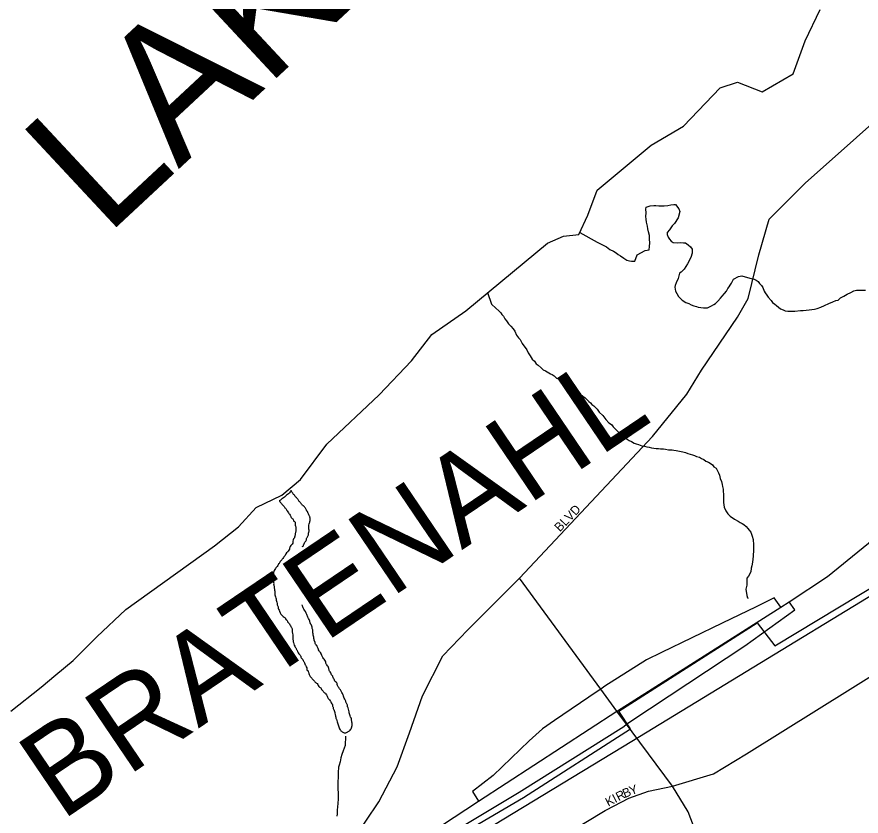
# Model space of a CAD drawing. Extents: x 2139079 to 2262683, y 1235796 to 1334992.
# Drawn here: x 2210756 to 2215487, y 1294375 to 1298857 of the extents above; entities that cross this region are included whole.
import ezdxf

# ---------------------------------------------------------------- set-up
doc = ezdxf.new("R2010")
doc.units = 0
for name, color, linetype in [('GM_X_City_Street', 7, 'Continuous'), ('GM_X_City_Street_Text', 7, 'Continuous'), ('GM_X_Interchange_Ramps', 7, 'Continuous'), ('GM_X_Interstate_Route', 7, 'Continuous'), ('GM_X_Major_Lake', 7, 'Continuous'), ('GM_X_Major_Lake_Text', 7, 'Continuous'), ('GM_X_Major_River', 7, 'Continuous'), ('GM_X_Minor_River', 7, 'Continuous'), ('GM_X_Rail_Line', 7, 'Continuous'), ('GM_X_State_Route', 7, 'Continuous')]:
    doc.layers.add(name, color=color, linetype=linetype)

msp = doc.modelspace()

# ---------------------------------------------------------------- linework, layer by layer
at = {"layer": 'GM_X_City_Street'}
for points in [[(2210765.7, 1293921.8), (2211801.2, 1293964.2), (2212304.8, 1294027), (2212399.2, 1294027), (2212466.8, 1294063.6), (2212638.5, 1294238.9), (2212784.6, 1294454.5), (2212886.8, 1294651.8), (2212956.2, 1294841.7), (2213029.3, 1295050), (2213142.5, 1295274.2), (2213283.1, 1295420.4), (2213573.5, 1295709), (2214317.9, 1296503.1), (2214511.4, 1296741.1), (2214593.2, 1296875), (2214794.1, 1297172.5), (2214853.5, 1297276.5), (2214913.2, 1297522), (2214972.6, 1297722.9), (2215173.4, 1297923.7), (2216341.1, 1298964.8), (2217218.8, 1299790.1), (2218141.2, 1300729.6)], [(2214060.3, 1294410.5), (2214185.1, 1294475.3), (2214295.7, 1294515.8), (2214429.8, 1294543.9), (2214660.6, 1294612.1), (2214845, 1294724.7), (2215629.5, 1295214.2), (2216726.2, 1295837.1), (2216761.4, 1295820.7)], [(2214027.8, 1295087.7), (2213573.5, 1295709)], [(2214203.9, 1294848.4), (2214173, 1294890.1), (2214118.6, 1294963.4), (2214027.8, 1295087.7)], [(2214644.6, 1293875.9), (2214639.6, 1293941.7), (2214628.6, 1294036), (2214601.9, 1294178), (2214518.7, 1294400), (2214429.8, 1294543.9), (2214203.9, 1294848.4)], [(2213265.1, 1293941.8), (2213266.3, 1293942.4), (2213845.7, 1294282), (2214053.1, 1294406.7), (2214060.3, 1294410.5)]]:
    msp.add_lwpolyline(points, dxfattribs=at)
at = {"layer": 'GM_X_Interchange_Ramps'}
for points in [[(2215037.1, 1295546.6), (2215000.7, 1295599.9), (2214898.3, 1295548.6), (2214709.2, 1295456.2), (2214367.8, 1295292.1), (2214283.8, 1295251), (2214050.7, 1295103), (2214027.8, 1295087.7)], [(2214173, 1294890.1), (2214195.9, 1294907.6), (2214836.1, 1295329.5), (2215115.1, 1295530.9), (2215084, 1295576.3)], [(2214027.8, 1295087.7), (2214007.8, 1295074.4), (2213768.2, 1294910.7), (2213702.4, 1294864.2), (2213626, 1294797), (2213425.5, 1294602.7), (2213309.6, 1294512.2), (2213343.6, 1294459.2)], [(2213134.5, 1294323.1), (2213168.7, 1294267.8), (2213571, 1294509.8), (2214156.8, 1294877.8), (2214173, 1294890.1)]]:
    msp.add_lwpolyline(points, dxfattribs=at)
at = {"layer": 'GM_X_Interstate_Route'}
for points in [[(2214122.3, 1294965.7), (2215037.1, 1295546.6), (2215084, 1295576.3), (2215299.7, 1295719.1), (2215728.5, 1296068), (2216029.7, 1296395.8), (2216265.8, 1296723.6), (2216403.8, 1296975), (2216521.9, 1297234.3), (2216598.9, 1297455.1), (2216727.2, 1297870.3), (2216829.9, 1298168.1), (2216968.5, 1298444.6), (2217135.4, 1298719.3)], [(2209268.7, 1291750.6), (2210765.4, 1292746), (2211168.5, 1293011), (2211346.1, 1293126.4), (2211567.6, 1293268.1), (2211821.2, 1293415.9), (2213292.4, 1294301), (2213595.9, 1294479.3), (2214194.6, 1294863.9), (2214129.9, 1294963.8), (2214905.3, 1295458), (2215003.2, 1295329.9), (2217276.8, 1296701.3)], [(2207701.2, 1290838), (2207916.4, 1290971.4), (2210778.7, 1292838.5), (2212470.3, 1293891), (2213134.5, 1294323.1), (2213343.6, 1294459.2), (2214118.6, 1294963.4), (2214122.3, 1294965.7)]]:
    msp.add_lwpolyline(points, dxfattribs=at)
at = {"layer": 'GM_X_Major_Lake'}
msp.add_lwpolyline([(2210722.2, 1294964.2), (2210891.3, 1295098.5), (2210972.9, 1295167.6), (2211070.4, 1295247), (2211203.4, 1295380.9), (2211366.3, 1295533.2), (2211862.2, 1295889.9), (2211997.5, 1295997.8), (2212096.7, 1296105.2), (2212240.5, 1296175), (2212345.9, 1296262.5), (2212492.3, 1296460.8), (2212786.3, 1296737.1), (2212966.9, 1296927.8), (2213081.7, 1297075.6), (2213270.9, 1297208.1), (2213730.4, 1297588.5), (2213818.3, 1297627.6), (2213904.5, 1297636.6), (2213955.5, 1297745.6), (2214008.2, 1297884.7), (2214310.5, 1298136.9), (2214492, 1298243.3), (2214696.4, 1298458.3), (2214794.4, 1298489.5), (2214933.5, 1298436.7), (2215107, 1298537), (2215173.2, 1298722.4), (2215257.6, 1298898)], dxfattribs=at)
at = {"layer": 'GM_X_Major_River'}
for points in [[(2212292.7, 1296200.8), (2212286.4, 1296193), (2212278.5, 1296182.9), (2212266.6, 1296174.8), (2212254.6, 1296162.6), (2212244.7, 1296156.5), (2212228.8, 1296144.3), (2212226.4, 1296142.8)], [(2212341, 1296137.2), (2212334.9, 1296143.2), (2212332.9, 1296149.2), (2212326.8, 1296155.2), (2212322.8, 1296161.2), (2212314.7, 1296167.1), (2212312.6, 1296173.1), (2212306.6, 1296179.1), (2212302.5, 1296185.1), (2212296.4, 1296193.1), (2212294.4, 1296199.1), (2212292.7, 1296200.8)], [(2212226.4, 1296142.8), (2212226.8, 1296142.3), (2212230.8, 1296136.3), (2212236.9, 1296130.4), (2212241, 1296124.4), (2212247, 1296118.4), (2212253.1, 1296110.4), (2212257.2, 1296104.4), (2212263.2, 1296100.4), (2212267.3, 1296092.4), (2212271.3, 1296086.4), (2212277.4, 1296076.5), (2212289.6, 1296058.5), (2212291.7, 1296052.5), (2212295.7, 1296046.5), (2212301.8, 1296042.5), (2212305.9, 1296034.5), (2212307.9, 1296028.5), (2212313.9, 1296026.6), (2212316, 1296020.6), (2212316.1, 1296006.5), (2212318.2, 1295996.5), (2212318.4, 1295970.3), (2212316.5, 1295964.3), (2212314.6, 1295956.3), (2212314.6, 1295950.2), (2212312.7, 1295944.2), (2212310.7, 1295936.1), (2212306.8, 1295930.1), (2212302.9, 1295916), (2212302.9, 1295910), (2212291.1, 1295891.8), (2212285.2, 1295881.7), (2212283.2, 1295871.7), (2212275.3, 1295861.6), (2212271.4, 1295855.5), (2212263.4, 1295845.4), (2212259.5, 1295837.3), (2212253.5, 1295831.2), (2212249.6, 1295825.2), (2212241.7, 1295815.1), (2212237.7, 1295809), (2212231.8, 1295803), (2212227.8, 1295794.9), (2212221.9, 1295788.8), (2212217.9, 1295780.8), (2212210, 1295770.6), (2212204.1, 1295762.6), (2212198.1, 1295752.5), (2212194.2, 1295740.4), (2212194.4, 1295722.3), (2212192.5, 1295716.3), (2212192.7, 1295692.2), (2212194.8, 1295682.1), (2212194.8, 1295672.1), (2212196.9, 1295664.1), (2212197, 1295658.1), (2212199, 1295650.1), (2212199.1, 1295644), (2212201.2, 1295638), (2212201.3, 1295622), (2212207.5, 1295597.9), (2212209.6, 1295591.9), (2212209.7, 1295579.8), (2212213.8, 1295567.8), (2212213.9, 1295559.8), (2212217.9, 1295551.8), (2212220, 1295545.8), (2212220.1, 1295539.8), (2212226.1, 1295529.8), (2212228.2, 1295523.8), (2212248.5, 1295493.8), (2212256.6, 1295487.9), (2212264.7, 1295475.9), (2212270.7, 1295471.9), (2212272.8, 1295463.9), (2212278.9, 1295457.9), (2212291.1, 1295437.9), (2212295.1, 1295431.9), (2212299.2, 1295419.9), (2212299.3, 1295407.9), (2212301.5, 1295391.8), (2212301.5, 1295385.8), (2212301.6, 1295375.8), (2212301.7, 1295369.8), (2212303.8, 1295361.7), (2212303.8, 1295355.7), (2212305.9, 1295347.7), (2212310, 1295333.7), (2212316.1, 1295321.7), (2212320.2, 1295315.7), (2212322.2, 1295309.7), (2212326.3, 1295303.7), (2212328.3, 1295297.7), (2212336.5, 1295285.7), (2212342.6, 1295277.7), (2212346.6, 1295271.7)], [(2212356.9, 1295885.9), (2212357.2, 1295886.3), (2212361.2, 1295892.4), (2212363.1, 1295898.4), (2212367.1, 1295906.5), (2212373, 1295914.6), (2212377, 1295920.6), (2212378.9, 1295926.7), (2212380.9, 1295934.7), (2212384.8, 1295940.8), (2212388.7, 1295948.8), (2212390.7, 1295954.9), (2212390.9, 1295956.9), (2212390.7, 1295958.9), (2212390.5, 1295960.9), (2212390.6, 1295962.9), (2212391, 1295964.4), (2212391.6, 1295965.9), (2212392.2, 1295967.4), (2212392.6, 1295969), (2212392.9, 1295978.4), (2212391.9, 1295988.1), (2212391.2, 1295997.7), (2212392.2, 1296007.1), (2212396.1, 1296019.2), (2212398.1, 1296027.2), (2212397.9, 1296051.3), (2212395.8, 1296057.3), (2212387.6, 1296073.3), (2212385.6, 1296079.4), (2212381.5, 1296085.3), (2212375.4, 1296097.3), (2212369.3, 1296105.3), (2212365.3, 1296111.3), (2212361.4, 1296114.4), (2212359.2, 1296115.8), (2212357.2, 1296117.3), (2212351.2, 1296123.3), (2212345.1, 1296131.2), (2212341, 1296137.2)], [(2212477, 1295254.7), (2212470.9, 1295264.7), (2212462.7, 1295280.7), (2212460.7, 1295286.7), (2212452.5, 1295298.7), (2212446.5, 1295306.7), (2212445.7, 1295308.6), (2212445.3, 1295310.6), (2212445, 1295312.7), (2212444.4, 1295314.7), (2212440.3, 1295322.7), (2212438.3, 1295328.7), (2212437, 1295330.4), (2212435.3, 1295331.7), (2212433.6, 1295333.1), (2212432.2, 1295334.7), (2212428.1, 1295342.7), (2212427.5, 1295345.1), (2212427.1, 1295347.7), (2212426.7, 1295350.2), (2212426, 1295352.7), (2212425.1, 1295354.7), (2212424, 1295356.7), (2212422.8, 1295358.6), (2212422, 1295360.7), (2212421.1, 1295365.1), (2212420.8, 1295369.7), (2212420.5, 1295374.3), (2212419.8, 1295378.8), (2212418.9, 1295381.8), (2212417.7, 1295384.7), (2212416.5, 1295387.7), (2212415.7, 1295390.8), (2212415.5, 1295392.7), (2212415.6, 1295394.8), (2212415.7, 1295396.8), (2212415.6, 1295398.8), (2212414.6, 1295401.8), (2212414, 1295403.3), (2212413.6, 1295404.8), (2212413.4, 1295408.3), (2212413.6, 1295411.8), (2212413.7, 1295415.4), (2212413.4, 1295418.9), (2212411.4, 1295426.9), (2212409.2, 1295440.9), (2212407.6, 1295444.6), (2212405.3, 1295448), (2212403, 1295451.3), (2212401.1, 1295454.9), (2212399, 1295460.9), (2212397, 1295468.9), (2212392.9, 1295476.9), (2212386.7, 1295490.9), (2212382.7, 1295500.9), (2212378.6, 1295508.9), (2212374.5, 1295518.9), (2212370.4, 1295524.9), (2212364.3, 1295534.9), (2212360.3, 1295542.9), (2212359.1, 1295545.9), (2212358.2, 1295548.9), (2212356.1, 1295554.9), (2212354.1, 1295559.1)], [(2212346.6, 1295271.7), (2212346.7, 1295265.7), (2212352.7, 1295259.7), (2212360.8, 1295247.7), (2212362.9, 1295241.7), (2212367, 1295233.7), (2212371.1, 1295223.7), (2212375.1, 1295217.7), (2212377.2, 1295211.7), (2212381.3, 1295201.7), (2212381.4, 1295193.7), (2212387.4, 1295189.7), (2212389.5, 1295181.7), (2212393.6, 1295169.7), (2212397.7, 1295161.7), (2212401.7, 1295155.7), (2212407.8, 1295147.7), (2212419.9, 1295135.8), (2212426, 1295127.8), (2212432.1, 1295121.8), (2212438.1, 1295117.8), (2212444.2, 1295107.8), (2212452.3, 1295097.9), (2212458.4, 1295093.9), (2212462.4, 1295085.9), (2212470.5, 1295077.9), (2212474.6, 1295071.9), (2212480.6, 1295066), (2212486.7, 1295060), (2212494.8, 1295048), (2212498.9, 1295038), (2212503, 1295032), (2212511.1, 1295022), (2212515.1, 1295016.1), (2212521.2, 1295004), (2212525.3, 1294998.1), (2212525.4, 1294992), (2212527.4, 1294986), (2212527.5, 1294978), (2212531.5, 1294972), (2212535.6, 1294962), (2212537.7, 1294952), (2212541.9, 1294935.9), (2212544, 1294923.9), (2212546, 1294917.9), (2212550.2, 1294903.9), (2212554.3, 1294891.9), (2212558.4, 1294881.9), (2212562.5, 1294869.8), (2212566.6, 1294859.8), (2212570.6, 1294853.8), (2212586.8, 1294843.9), (2212592.8, 1294842), (2212598.8, 1294842), (2212606.8, 1294846.1), (2212612.7, 1294850.2), (2212620.7, 1294854.2), (2212626.7, 1294862.3), (2212630.6, 1294868.4), (2212632.6, 1294874.4), (2212634.5, 1294882.5), (2212634.4, 1294896.5), (2212632.3, 1294906.6), (2212630.2, 1294914.6), (2212630.1, 1294920.6), (2212626.1, 1294930.6), (2212621.9, 1294942.6), (2212615.7, 1294966.7), (2212611.6, 1294982.7), (2212609.5, 1294988.7), (2212605.4, 1295004.7), (2212601.3, 1295010.7), (2212599.2, 1295018.7), (2212595.2, 1295026.7), (2212587, 1295046.8), (2212584.9, 1295052.8), (2212574.7, 1295072.8), (2212570.7, 1295078.8), (2212562.5, 1295092.8), (2212556.4, 1295100.7), (2212552.4, 1295106.7), (2212550.3, 1295118.8), (2212546.2, 1295124.7), (2212538.1, 1295132.7), (2212534, 1295142.7), (2212527.9, 1295152.7), (2212525.9, 1295160.7), (2212519.8, 1295166.7), (2212515.7, 1295178.7), (2212507.6, 1295188.7), (2212505.5, 1295194.7), (2212503.5, 1295202.7), (2212493.3, 1295222.7), (2212489.2, 1295228.7), (2212487.1, 1295236.7), (2212485.1, 1295244.7), (2212477, 1295254.7)]]:
    msp.add_spline(points, degree=3, dxfattribs=at)
at = {"layer": 'GM_X_Minor_River'}
for points in [[(2213910.3, 1297648.4), (2214008.3, 1297593.7), (2214038.7, 1297578.2), (2214061, 1297566.6), (2214079.4, 1297552.9), (2214099.7, 1297543.2), (2214113.9, 1297533.4), (2214126.2, 1297523.6), (2214138.4, 1297515.8), (2214156.7, 1297504.1), (2214175, 1297492.4), (2214189.1, 1297488.7), (2214201.2, 1297486.9), (2214219.3, 1297487.2), (2214232.6, 1297521.7), (2214276.3, 1297546.6), (2214300.3, 1297551.1), (2214301.9, 1297569.2), (2214303.5, 1297589.4), (2214301.1, 1297609.4), (2214300.7, 1297631.5), (2214296.2, 1297651.5), (2214291.9, 1297667.5), (2214289.6, 1297683.6), (2214285.1, 1297705.6), (2214282.8, 1297721.6), (2214280.4, 1297737.7), (2214282, 1297757.8), (2214281.6, 1297777.9), (2214283.4, 1297790), (2214305.3, 1297796.4), (2214325.4, 1297798.8), (2214337.4, 1297799.1), (2214353.5, 1297797.4), (2214365.5, 1297797.6), (2214383.6, 1297797.9), (2214403.7, 1297798.3), (2214421.7, 1297802.7), (2214437.7, 1297805), (2214447.7, 1297805.2), (2214466.3, 1297779.5), (2214470.6, 1297765.5), (2214461.3, 1297729.1), (2214441.9, 1297698.6), (2214428.1, 1297684.2), (2214412.5, 1297661.8), (2214400.7, 1297647.5), (2214401, 1297635.5), (2214405.3, 1297621.5), (2214413.6, 1297609.6), (2214421.8, 1297599.7), (2214434, 1297591.9), (2214456.1, 1297590.3), (2214476.2, 1297590.7), (2214492.3, 1297589), (2214502.3, 1297589.2), (2214518.6, 1297577.5), (2214530.9, 1297567.7), (2214541.2, 1297553.8), (2214539.7, 1297531.7), (2214532.1, 1297507.4), (2214514.8, 1297470.9), (2214495.3, 1297442.4), (2214479.6, 1297426), (2214469.7, 1297419.8), (2214462.3, 1297389.5), (2214450.7, 1297365.1), (2214445, 1297350.9), (2214443.2, 1297340.9), (2214447.6, 1297318.8), (2214453.9, 1297304.9), (2214464.3, 1297289), (2214472.6, 1297279.1), (2214484.8, 1297267.3), (2214505.2, 1297255.6), (2214521.3, 1297249.9), (2214535.6, 1297242.2), (2214549.7, 1297236.4), (2214563.9, 1297232.7), (2214574, 1297228.8), (2214588.1, 1297227.1), (2214604.2, 1297225.4), (2214614.2, 1297225.6), (2214626.2, 1297225.8), (2214648.1, 1297236.3), (2214662, 1297244.6), (2214672, 1297248.8), (2214683.7, 1297263.1), (2214699.5, 1297279.5), (2214709.3, 1297289.8), (2214721, 1297306.1), (2214732.8, 1297318.3), (2214740.5, 1297332.6), (2214748.4, 1297342.8), (2214754.2, 1297352.9), (2214760, 1297363.1), (2214771.6, 1297385.4), (2214799.4, 1297400)], [(2214799.4, 1297400), (2214819.4, 1297404.4), (2214876, 1297387.4), (2214888, 1297385.7), (2214898.2, 1297379.8), (2214910.4, 1297372), (2214918.6, 1297362.1), (2214928.9, 1297350.3), (2214937.2, 1297338.4), (2214943.6, 1297318.4), (2214949.9, 1297308.5), (2214958.1, 1297296.6), (2214966.4, 1297284.7), (2214982.8, 1297266.9), (2214991.1, 1297255), (2215003.4, 1297245.2), (2215013.6, 1297237.4), (2215023.8, 1297229.5), (2215036, 1297219.7), (2215050.2, 1297214), (2215062.4, 1297208.2), (2215076.5, 1297206.4), (2215092.5, 1297206.8), (2215116.6, 1297207.2), (2215146.7, 1297209.8), (2215162.7, 1297210.1), (2215178.8, 1297212.4), (2215196.8, 1297214.8), (2215210.8, 1297215.1), (2215226.8, 1297217.4), (2215240.8, 1297221.7), (2215260.8, 1297228.1), (2215282.6, 1297238.6), (2215306.5, 1297249.1), (2215328.4, 1297259.6), (2215346.3, 1297265.9), (2215358.3, 1297268.2), (2215372.1, 1297280.5), (2215390, 1297290.9), (2215409.9, 1297301.3), (2215429.7, 1297311.8), (2215445.6, 1297320.1), (2215461.6, 1297324.5), (2215511.8, 1297323.4)], [(2213392.4, 1297310.8), (2213415, 1297246.5), (2213439.5, 1297222.9), (2213455.9, 1297209.1), (2213468.2, 1297197.3), (2213474.4, 1297187.4), (2213482.6, 1297177.5), (2213491, 1297163.6), (2213499.2, 1297151.7), (2213511.6, 1297135.9), (2213523.9, 1297122), (2213536.3, 1297108.2), (2213546.6, 1297094.3), (2213555.1, 1297072.4), (2213567.5, 1297056.6), (2213575.7, 1297046.6), (2213581.9, 1297036.7), (2213588.2, 1297024.8), (2213596.5, 1297012.9), (2213604.7, 1297003), (2213613, 1296989.1), (2213621.4, 1296973.2), (2213631.8, 1296955.3), (2213644.2, 1296937.4), (2213656.5, 1296925.6), (2213666.8, 1296911.8), (2213677, 1296903.9), (2213693.4, 1296888.2), (2213705.6, 1296878.3), (2213717.8, 1296872.6), (2213728, 1296866.7), (2213746.3, 1296855), (2213756.4, 1296851.2), (2213766.6, 1296843.4), (2213780.9, 1296831.6), (2213803.1, 1296824), (2213821.3, 1296818.3), (2213835.5, 1296812.5), (2213849.7, 1296806.8), (2213859.8, 1296805), (2213888.6, 1296767.3), (2213905, 1296753.6), (2213915.3, 1296741.7), (2213927.6, 1296729.9), (2213939.8, 1296720.1), (2213950.1, 1296710.2), (2213960.3, 1296700.4), (2213970.5, 1296692.6), (2213978.7, 1296682.7), (2213988.9, 1296674.8), (2214007.4, 1296657.1), (2214019.8, 1296639.3), (2214040.2, 1296621.6), (2214056.7, 1296599.8), (2214073.2, 1296580), (2214087.5, 1296570.2), (2214097.7, 1296558.4), (2214116.2, 1296538.6), (2214128.5, 1296526.8), (2214149, 1296509.1), (2214165.3, 1296497.4), (2214175.5, 1296489.5), (2214187.7, 1296481.7), (2214199.8, 1296475.9), (2214216.1, 1296466.2), (2214226.2, 1296462.4), (2214240.3, 1296458.6), (2214258.6, 1296451), (2214272.7, 1296449.2), (2214286.8, 1296445.5), (2214298.9, 1296443.7), (2214313, 1296440), (2214325.1, 1296438.2), (2214339.2, 1296436.5), (2214351.2, 1296436.7), (2214363.3, 1296434.9), (2214379.4, 1296435.2), (2214391.5, 1296433.4), (2214407.6, 1296429.8), (2214427.7, 1296428.1), (2214437.8, 1296426.3), (2214449.9, 1296424.5), (2214488.2, 1296417.2), (2214502.3, 1296413.5), (2214516.5, 1296407.7), (2214528.6, 1296404), (2214542.8, 1296400.2), (2214552.9, 1296396.4), (2214565, 1296390.6), (2214581.2, 1296386.9), (2214593.3, 1296381.1), (2214605.5, 1296375.3), (2214617.8, 1296365.5), (2214631.9, 1296359.8), (2214642.1, 1296353.9), (2214654.3, 1296344.1), (2214662.6, 1296334.2), (2214674.8, 1296326.4), (2214687.4, 1296300.5), (2214693.7, 1296286.6)], [(2214693.7, 1296286.6), (2214698.1, 1296268.6), (2214704.5, 1296250.6), (2214708.8, 1296234.6), (2214711.1, 1296222.6), (2214713.4, 1296208.6), (2214713.6, 1296194.5), (2214715.9, 1296180.5), (2214716.3, 1296162.4), (2214716.9, 1296134.3), (2214719.4, 1296108.2), (2214729.9, 1296086.3), (2214740.3, 1296070.4), (2214752.6, 1296056.6), (2214777, 1296041), (2214797.3, 1296029.4), (2214809.6, 1296021.6), (2214819.7, 1296015.7), (2214829.9, 1296009.9), (2214842.2, 1295998.1), (2214852.4, 1295988.2), (2214860.6, 1295978.3), (2214868.9, 1295966.4), (2214873.1, 1295956.5), (2214877.4, 1295944.5), (2214881.8, 1295926.5), (2214884.4, 1295896.4), (2214885, 1295868.3), (2214881.7, 1295832.1), (2214878.3, 1295799.8), (2214874.8, 1295777.7), (2214871, 1295765.5), (2214869.4, 1295745.4), (2214855.9, 1295721), (2214846.1, 1295708.8), (2214846.9, 1295670.6), (2214841.3, 1295648.4), (2214846, 1295612.3), (2214850.3, 1295598.3), (2214854.4, 1295596.4)], [(2212597.1, 1294823.1), (2212596.2, 1294770.8), (2212584.7, 1294740.5), (2212577.1, 1294720.2), (2212571.5, 1294702), (2212567.9, 1294679.8), (2212562.3, 1294661.7), (2212558.5, 1294649.5), (2212557.1, 1294619.4), (2212555.4, 1294605.3), (2212555.6, 1294595.2), (2212554.2, 1294565.1), (2212554.5, 1294551), (2212555, 1294524.9), (2212555.4, 1294506.8), (2212555.8, 1294484.7), (2212556.2, 1294464.6), (2212554.5, 1294452.5), (2212554.7, 1294442.5), (2212552.9, 1294430.4), (2212551.5, 1294404.3), (2212549.8, 1294388.1), (2212548.1, 1294374.1)]]:
    msp.add_lwpolyline(points, dxfattribs=at)
at = {"layer": 'GM_X_Rail_Line'}
msp.add_lwpolyline([(2203228.1, 1287651), (2204195.4, 1288303.3), (2204797, 1288709.8), (2205631.8, 1289275), (2206337, 1289750.9), (2206850, 1290098.6), (2207481.5, 1290525.3), (2207991.6, 1290871.6), (2208474.1, 1291197), (2209455.6, 1291861.2), (2209862.1, 1292136), (2210353.6, 1292453.2), (2211370.1, 1293079.5), (2212078.2, 1293511.4), (2212986.7, 1294057.2), (2214201.7, 1294795.7), (2216244.5, 1296039.8), (2216686.9, 1296308.3), (2217205.9, 1296624.7), (2218314.7, 1297298.6)], dxfattribs=at)

# ---------------------------------------------------------------- texts
at = {"layer": 'GM_X_City_Street_Text'}
for s, rotation, p in [('BLVD', 46.0845, (2213799, 1295966)), ('B', 23.5877, (2214162.8, 1294476)), ('Y', 19.8655, (2214198.3, 1294491.5)), ('K', 27.386, (2214069.8, 1294427.8)), ('I', 27.386, (2214108.9, 1294448)), ('R', 27.3796, (2214128.4, 1294458.1))]:
    msp.add_text(s, height=50, rotation=rotation, dxfattribs=at).set_placement(p)
at = {"layer": 'GM_X_Major_Lake_Text'}
msp.add_text('LAKE ERIE', height=750, rotation=42.9802, dxfattribs=at).set_placement((2211253.2, 1297621))
at = {"layer": 'GM_X_State_Route'}
msp.add_text('BRATENAHL', height=500, rotation=34.1113, dxfattribs=at).set_placement((2211003.7, 1294344.6))

doc.saveas('drawing.dxf')
